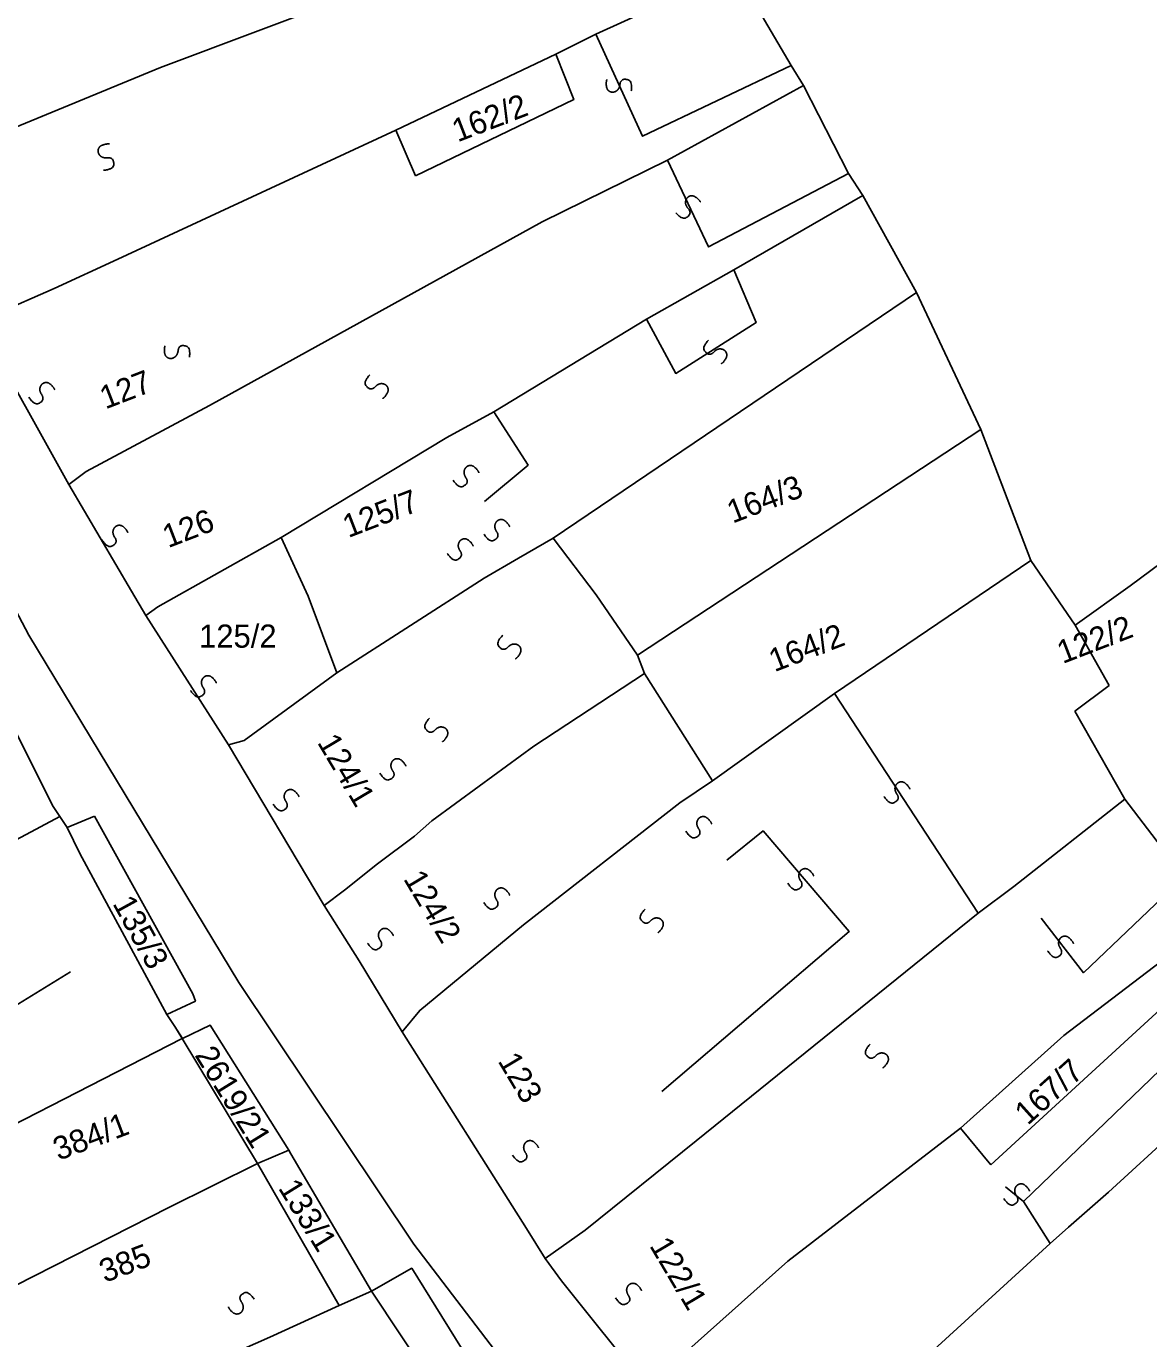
# Model space of a CAD drawing. Extents: x -581999 to -572728, y -1219553 to -1212032.
# Drawn here: x -577479.6 to -577382.6, y -1215803.1 to -1215689.6 of the extents above; entities that cross this region are included whole.
import ezdxf

# ---------------------------------------------------------------- set-up
doc = ezdxf.new("R2010")
doc.units = 0
for name, color, linetype in [('Vrstva 1', 7, 'Continuous'), ('Vrstva 2', 7, 'Continuous'), ('Vrstva 4', 7, 'Continuous'), ('Vrstva 6', 7, 'Continuous')]:
    doc.layers.add(name, color=color, linetype=linetype)

msp = doc.modelspace()

# ---------------------------------------------------------------- linework, layer by layer
at = {"layer": 'Vrstva 1'}
for p, q in [((-577474.479, -1215728.124), (-577475.958, -1215729.249)), ((-577468.275, -1215739.842), (-577469.308, -1215740.589)), ((-577481.907, -1215747.92), (-577477.385, -1215757.007)), ((-577460.819, -1215751.383), (-577462.159, -1215751.762)), ((-577477.385, -1215757.007), (-577476.755, -1215757.963)), ((-577507.598, -1215774.39), (-577476.755, -1215757.963)), ((-577476.123, -1215758.918), (-577476.755, -1215757.963)), ((-577476.123, -1215758.918), (-577473.744, -1215757.93)), ((-577473.744, -1215757.93), (-577465.258, -1215773.299)), ((-577475.024, -1215761.158), (-577476.123, -1215758.918)), ((-577452.134, -1215764.323), (-577453.896, -1215765.669)), ((-577421.749, -1215786.002), (-577397.389, -1215766.323)), ((-577431.335, -1215793.716), (-577421.749, -1215786.002)), ((-577431.335, -1215793.716), (-577434.793, -1215796.187))]:
    msp.add_line(p, q, dxfattribs=at)
for points in [[(-577468.038, -1215693.198), (-577433.831, -1215680.339), (-577425.062, -1215680.368), (-577420.535, -1215682.912), (-577418.354, -1215684.817)], [(-577418.354, -1215684.817), (-577430.438, -1215690.313)], [(-577418.354, -1215684.817), (-577413.545, -1215693.037)], [(-577430.438, -1215690.313), (-577433.893, -1215692.041)], [(-577433.893, -1215692.041), (-577447.706, -1215698.639)], [(-577445.994, -1215702.58), (-577432.338, -1215695.982), (-577433.893, -1215692.041)], [(-577415.225, -1215820.765), (-577417.003, -1215818.866), (-577424.293, -1215809.474), (-577425.981, -1215807.36), (-577433.385, -1215798.112), (-577434.793, -1215796.187), (-577436.416, -1215793.567), (-577447.16, -1215776.59), (-577450.88, -1215770.44), (-577453.896, -1215765.669), (-577462.159, -1215751.762), (-577469.308, -1215740.589), (-577470.545, -1215738.478), (-577475.958, -1215729.249), (-577483.606, -1215715.574), (-577485.422, -1215712.277), (-577489.417, -1215702.652), (-577494.758, -1215693.186)], [(-577488.601, -1215701.674), (-577468.038, -1215693.198)], [(-577413.545, -1215693.037), (-577412.464, -1215694.765)], [(-577424.24, -1215701.209), (-577412.464, -1215694.765)], [(-577412.464, -1215694.765), (-577408.591, -1215702.365)], [(-577447.706, -1215698.639), (-577471.725, -1215709.791), (-577477.219, -1215712.305)], [(-577445.994, -1215702.58), (-577447.706, -1215698.639)], [(-577435.07, -1215706.551), (-577424.24, -1215701.209)], [(-577408.591, -1215702.365), (-577407.35, -1215704.266)], [(-577407.35, -1215704.266), (-577418.498, -1215710.713)], [(-577402.699, -1215712.659), (-577407.35, -1215704.266)], [(-577463.808, -1215722.432), (-577435.07, -1215706.551)], [(-577496.282, -1215710.3), (-577479.426, -1215742.275), (-577461.278, -1215772.317), (-577446.155, -1215794.936), (-577420.966, -1215827.922), (-577400.326, -1215855.892), (-577397.913, -1215860.961)], [(-577418.498, -1215710.713), (-577426.034, -1215714.958)], [(-577477.219, -1215712.305), (-577482.242, -1215714.502)], [(-577434.118, -1215733.903), (-577402.699, -1215712.659)], [(-577397.141, -1215724.499), (-577402.699, -1215712.659)], [(-577426.034, -1215714.958), (-577439.227, -1215722.98)], [(-577474.479, -1215728.124), (-577463.808, -1215722.432)], [(-577439.227, -1215722.98), (-577443.31, -1215725.181)], [(-577426.826, -1215744.009), (-577397.141, -1215724.499)], [(-577392.841, -1215735.842), (-577397.141, -1215724.499)], [(-577443.31, -1215725.181), (-577457.602, -1215733.833)], [(-577457.602, -1215733.833), (-577468.275, -1215739.842)], [(-577457.602, -1215733.833), (-577455.28, -1215738.899)], [(-577437.102, -1215735.633), (-577434.118, -1215733.903)], [(-577430.398, -1215738.784), (-577434.118, -1215733.903)], [(-577440.085, -1215737.362), (-577437.102, -1215735.633)], [(-577409.804, -1215747.327), (-577392.841, -1215735.842)], [(-577392.841, -1215735.842), (-577389.002, -1215741.426)], [(-577384.258, -1215738.017), (-577380.685, -1215735.373)], [(-577452.809, -1215745.544), (-577440.085, -1215737.362)], [(-577389.002, -1215741.426), (-577384.258, -1215738.017)], [(-577455.28, -1215738.899), (-577452.809, -1215745.544)], [(-577426.826, -1215744.009), (-577430.398, -1215738.784)], [(-577389.002, -1215741.426), (-577386.058, -1215746.649)], [(-577426.208, -1215745.591), (-577426.826, -1215744.009)], [(-577460.819, -1215751.383), (-577452.809, -1215745.544)], [(-577435.789, -1215751.885), (-577426.208, -1215745.591)], [(-577420.331, -1215754.882), (-577426.208, -1215745.591)], [(-577386.058, -1215746.649), (-577389.043, -1215748.853)], [(-577409.804, -1215747.327), (-577420.331, -1215754.882)], [(-577389.043, -1215748.853), (-577384.704, -1215756.449)], [(-577440.499, -1215755.34), (-577435.789, -1215751.885)], [(-577423.157, -1215756.77), (-577420.331, -1215754.882)], [(-577444.59, -1215758.339), (-577440.499, -1215755.34)], [(-577360.719, -1215755.42), (-577396.277, -1215788.068)], [(-577436.674, -1215767.319), (-577423.157, -1215756.77)], [(-577384.704, -1215756.449), (-577394.29, -1215764.005)], [(-577384.704, -1215756.449), (-577379.584, -1215763.188)], [(-577446.104, -1215759.665), (-577444.59, -1215758.339)], [(-577358.87, -1215757.912), (-577393.478, -1215791.234)], [(-577449.285, -1215762.063), (-577446.104, -1215759.665)], [(-577467.49, -1215775.069), (-577475.024, -1215761.158)], [(-577452.134, -1215764.323), (-577449.285, -1215762.063)], [(-577394.29, -1215764.005), (-577397.389, -1215766.323)], [(-577447.16, -1215776.59), (-577445.634, -1215774.72), (-577436.674, -1215767.319)], [(-577376.787, -1215766.829), (-577389.984, -1215776.902), (-577398.919, -1215784.902)], [(-577465.258, -1215773.299), (-577465.025, -1215773.915), (-577467.49, -1215775.069)], [(-577467.49, -1215775.069), (-577466.813, -1215776.114)], [(-577466.813, -1215776.114), (-577466.144, -1215777.146)], [(-577466.18, -1215777.164), (-577466.813, -1215776.114)], [(-577466.144, -1215777.146), (-577463.764, -1215775.991), (-577456.952, -1215786.805)], [(-577490.032, -1215789.369), (-577466.18, -1215777.164)], [(-577466.18, -1215777.164), (-577466.144, -1215777.146)], [(-577459.671, -1215787.958), (-577466.18, -1215777.164)], [(-577398.919, -1215784.902), (-577413.845, -1215796.392)], [(-577396.277, -1215788.068), (-577398.919, -1215784.902)], [(-577386.114, -1215790.453), (-577380.336, -1215785.123)], [(-577459.671, -1215787.958), (-577456.952, -1215786.805)], [(-577456.952, -1215786.805), (-577456.785, -1215787.123), (-577449.81, -1215798.999)], [(-577467.321, -1215791.752), (-577459.671, -1215787.958)], [(-577452.614, -1215800.25), (-577459.671, -1215787.958)], [(-577391.151, -1215794.873), (-577393.478, -1215791.234)], [(-577389.591, -1215793.467), (-577386.114, -1215790.453)], [(-577480.581, -1215798.517), (-577467.321, -1215791.752)], [(-577391.151, -1215794.873), (-577389.591, -1215793.467)], [(-577408.917, -1215811.092), (-577391.151, -1215794.873)], [(-577449.81, -1215798.999), (-577446.325, -1215797.019), (-577434.643, -1215815.868), (-577437.449, -1215817.602)], [(-577413.845, -1215796.392), (-577422.648, -1215804.265)], [(-577452.614, -1215800.25), (-577449.81, -1215798.999)], [(-577437.449, -1215817.602), (-577449.81, -1215798.999)], [(-577458.586, -1215802.977), (-577452.614, -1215800.25)], [(-577472.01, -1215808.911), (-577458.586, -1215802.977)]]:
    msp.add_lwpolyline(points, dxfattribs=at)
at = {"layer": 'Vrstva 4'}
for points in [[(-577430.438, -1215690.313), (-577426.404, -1215699.147), (-577413.545, -1215693.037)], [(-577424.24, -1215701.209), (-577420.687, -1215708.719), (-577408.591, -1215702.365)], [(-577426.034, -1215714.958), (-577423.514, -1215719.662), (-577416.569, -1215715.256), (-577418.498, -1215710.713)], [(-577439.227, -1215722.98), (-577436.277, -1215727.575), (-577440.05, -1215730.724)], [(-577397.389, -1215766.323), (-577409.804, -1215747.327)], [(-577419.112, -1215761.723), (-577415.968, -1215759.204), (-577408.526, -1215767.893), (-577424.719, -1215781.751)], [(-577391.935, -1215766.756), (-577388.277, -1215771.472), (-577379.584, -1215763.188)], [(-577475.827, -1215771.391), (-577481.441, -1215774.858)], [(-577393.478, -1215791.234), (-577395.035, -1215789.966)]]:
    msp.add_lwpolyline(points, dxfattribs=at)
at = {"layer": 'Vrstva 6'}
for points in [[(-577427.357, -1215695.227), (-577427.262, -1215694.376), (-577427.992, -1215694.164), (-577428.309, -1215694.418), (-577428.354, -1215694.834), (-577428.505, -1215695.141), (-577428.754, -1215695.308), (-577428.981, -1215695.352), (-577429.244, -1215695.296), (-577429.499, -1215695.032), (-577429.539, -1215694.422), (-577429.469, -1215694.253)], [(-577472.967, -1215702.095), (-577472.116, -1215702.006), (-577472.064, -1215701.248), (-577472.38, -1215700.992), (-577472.796, -1215701.037), (-577473.128, -1215700.955), (-577473.345, -1215700.747), (-577473.436, -1215700.535), (-577473.437, -1215700.266), (-577473.234, -1215699.961), (-577472.646, -1215699.791), (-577472.466, -1215699.824)], [(-577423.513, -1215705.765), (-577422.937, -1215706.397), (-577422.295, -1215705.99), (-577422.276, -1215705.584), (-577422.559, -1215705.276), (-577422.689, -1215704.959), (-577422.65, -1215704.661), (-577422.533, -1215704.462), (-577422.317, -1215704.302), (-577421.951, -1215704.285), (-577421.466, -1215704.658), (-577421.386, -1215704.823)], [(-577465.54, -1215718.251), (-577465.445, -1215717.4), (-577466.175, -1215717.188), (-577466.492, -1215717.442), (-577466.537, -1215717.858), (-577466.688, -1215718.165), (-577466.937, -1215718.332), (-577467.164, -1215718.376), (-577467.427, -1215718.32), (-577467.682, -1215718.056), (-577467.722, -1215717.446), (-577467.652, -1215717.277)], [(-577420.679, -1215716.769), (-577421.266, -1215717.391), (-577420.811, -1215718), (-577420.405, -1215717.988), (-577420.119, -1215717.683), (-577419.813, -1215717.529), (-577419.513, -1215717.545), (-577419.306, -1215717.647), (-577419.13, -1215717.85), (-577419.085, -1215718.214), (-577419.42, -1215718.726), (-577419.578, -1215718.818)], [(-577449.941, -1215719.77), (-577450.528, -1215720.392), (-577450.073, -1215721.001), (-577449.667, -1215720.989), (-577449.381, -1215720.684), (-577449.075, -1215720.53), (-577448.775, -1215720.546), (-577448.568, -1215720.648), (-577448.392, -1215720.851), (-577448.347, -1215721.215), (-577448.682, -1215721.727), (-577448.84, -1215721.819)], [(-577479.422, -1215721.708), (-577478.942, -1215722.415), (-577478.248, -1215722.104), (-577478.171, -1215721.704), (-577478.407, -1215721.359), (-577478.492, -1215721.027), (-577478.41, -1215720.737), (-577478.266, -1215720.557), (-577478.03, -1215720.429), (-577477.665, -1215720.465), (-577477.238, -1215720.904), (-577477.183, -1215721.077)], [(-577442.765, -1215728.881), (-577442.285, -1215729.588), (-577441.591, -1215729.277), (-577441.514, -1215728.877), (-577441.75, -1215728.532), (-577441.835, -1215728.2), (-577441.753, -1215727.91), (-577441.609, -1215727.73), (-577441.373, -1215727.602), (-577441.008, -1215727.638), (-577440.581, -1215728.077), (-577440.526, -1215728.25)], [(-577440.105, -1215733.55), (-577439.625, -1215734.257), (-577438.931, -1215733.946), (-577438.854, -1215733.546), (-577439.09, -1215733.201), (-577439.175, -1215732.869), (-577439.093, -1215732.579), (-577438.949, -1215732.399), (-577438.713, -1215732.271), (-577438.348, -1215732.307), (-577437.921, -1215732.746), (-577437.866, -1215732.919)], [(-577473.104, -1215734.049), (-577472.624, -1215734.756), (-577471.93, -1215734.445), (-577471.853, -1215734.045), (-577472.089, -1215733.7), (-577472.174, -1215733.368), (-577472.092, -1215733.078), (-577471.948, -1215732.898), (-577471.712, -1215732.77), (-577471.347, -1215732.806), (-577470.92, -1215733.245), (-577470.865, -1215733.418)], [(-577443.264, -1215735.218), (-577442.784, -1215735.925), (-577442.09, -1215735.614), (-577442.013, -1215735.214), (-577442.249, -1215734.869), (-577442.334, -1215734.537), (-577442.252, -1215734.247), (-577442.108, -1215734.067), (-577441.872, -1215733.939), (-577441.507, -1215733.975), (-577441.08, -1215734.414), (-577441.025, -1215734.587)], [(-577438.469, -1215742.283), (-577439.056, -1215742.905), (-577438.601, -1215743.514), (-577438.195, -1215743.502), (-577437.909, -1215743.197), (-577437.603, -1215743.043), (-577437.303, -1215743.059), (-577437.096, -1215743.161), (-577436.92, -1215743.364), (-577436.875, -1215743.728), (-577437.21, -1215744.24), (-577437.368, -1215744.332)], [(-577465.457, -1215747.056), (-577464.977, -1215747.763), (-577464.283, -1215747.452), (-577464.206, -1215747.052), (-577464.442, -1215746.707), (-577464.527, -1215746.375), (-577464.445, -1215746.085), (-577464.301, -1215745.905), (-577464.065, -1215745.777), (-577463.7, -1215745.813), (-577463.273, -1215746.252), (-577463.218, -1215746.425)], [(-577444.788, -1215749.453), (-577445.375, -1215750.075), (-577444.92, -1215750.684), (-577444.514, -1215750.672), (-577444.228, -1215750.367), (-577443.922, -1215750.213), (-577443.622, -1215750.229), (-577443.415, -1215750.331), (-577443.239, -1215750.534), (-577443.194, -1215750.898), (-577443.529, -1215751.41), (-577443.687, -1215751.502)], [(-577449.083, -1215754.229), (-577448.603, -1215754.936), (-577447.909, -1215754.625), (-577447.832, -1215754.225), (-577448.068, -1215753.88), (-577448.153, -1215753.548), (-577448.071, -1215753.258), (-577447.927, -1215753.078), (-577447.691, -1215752.95), (-577447.326, -1215752.986), (-577446.899, -1215753.425), (-577446.844, -1215753.598)], [(-577405.523, -1215756.23), (-577405.043, -1215756.937), (-577404.349, -1215756.626), (-577404.272, -1215756.226), (-577404.508, -1215755.881), (-577404.593, -1215755.549), (-577404.511, -1215755.259), (-577404.367, -1215755.079), (-577404.131, -1215754.951), (-577403.766, -1215754.987), (-577403.339, -1215755.426), (-577403.284, -1215755.599)], [(-577458.307, -1215756.895), (-577457.827, -1215757.602), (-577457.133, -1215757.291), (-577457.056, -1215756.891), (-577457.292, -1215756.546), (-577457.377, -1215756.214), (-577457.295, -1215755.924), (-577457.151, -1215755.744), (-577456.915, -1215755.616), (-577456.55, -1215755.652), (-577456.123, -1215756.091), (-577456.068, -1215756.264)], [(-577422.648, -1215759.232), (-577422.168, -1215759.939), (-577421.474, -1215759.628), (-577421.397, -1215759.228), (-577421.633, -1215758.883), (-577421.718, -1215758.551), (-577421.636, -1215758.261), (-577421.492, -1215758.081), (-577421.256, -1215757.953), (-577420.891, -1215757.989), (-577420.464, -1215758.428), (-577420.409, -1215758.601)], [(-577413.836, -1215763.735), (-577413.356, -1215764.442), (-577412.662, -1215764.131), (-577412.585, -1215763.731), (-577412.821, -1215763.386), (-577412.906, -1215763.054), (-577412.824, -1215762.764), (-577412.68, -1215762.584), (-577412.444, -1215762.456), (-577412.079, -1215762.492), (-577411.652, -1215762.931), (-577411.597, -1215763.104)], [(-577440.105, -1215765.402), (-577439.625, -1215766.109), (-577438.931, -1215765.798), (-577438.854, -1215765.398), (-577439.09, -1215765.053), (-577439.175, -1215764.721), (-577439.093, -1215764.431), (-577438.949, -1215764.251), (-577438.713, -1215764.123), (-577438.348, -1215764.159), (-577437.921, -1215764.598), (-577437.866, -1215764.771)], [(-577426.166, -1215765.963), (-577426.753, -1215766.585), (-577426.298, -1215767.194), (-577425.892, -1215767.182), (-577425.606, -1215766.877), (-577425.3, -1215766.723), (-577425, -1215766.739), (-577424.793, -1215766.841), (-577424.617, -1215767.044), (-577424.572, -1215767.408), (-577424.907, -1215767.92), (-577425.065, -1215768.012)], [(-577450.16, -1215768.901), (-577449.68, -1215769.608), (-577448.986, -1215769.297), (-577448.909, -1215768.897), (-577449.145, -1215768.552), (-577449.23, -1215768.22), (-577449.148, -1215767.93), (-577449.004, -1215767.75), (-577448.768, -1215767.622), (-577448.403, -1215767.658), (-577447.976, -1215768.097), (-577447.921, -1215768.27)], [(-577391.39, -1215769.571), (-577390.91, -1215770.278), (-577390.216, -1215769.967), (-577390.139, -1215769.567), (-577390.375, -1215769.222), (-577390.46, -1215768.89), (-577390.378, -1215768.6), (-577390.234, -1215768.42), (-577389.998, -1215768.292), (-577389.633, -1215768.328), (-577389.206, -1215768.767), (-577389.151, -1215768.94)], [(-577406.713, -1215777.636), (-577407.3, -1215778.258), (-577406.845, -1215778.867), (-577406.439, -1215778.855), (-577406.153, -1215778.55), (-577405.847, -1215778.396), (-577405.547, -1215778.412), (-577405.34, -1215778.514), (-577405.164, -1215778.717), (-577405.119, -1215779.081), (-577405.454, -1215779.593), (-577405.612, -1215779.685)], [(-577437.611, -1215787.248), (-577437.131, -1215787.955), (-577436.437, -1215787.644), (-577436.36, -1215787.244), (-577436.596, -1215786.899), (-577436.681, -1215786.567), (-577436.599, -1215786.277), (-577436.455, -1215786.097), (-577436.219, -1215785.969), (-577435.854, -1215786.005), (-577435.427, -1215786.444), (-577435.372, -1215786.617)], [(-577395.178, -1215790.986), (-577394.698, -1215791.693), (-577394.004, -1215791.382), (-577393.927, -1215790.982), (-577394.163, -1215790.637), (-577394.248, -1215790.305), (-577394.166, -1215790.015), (-577394.022, -1215789.835), (-577393.786, -1215789.707), (-577393.421, -1215789.743), (-577392.994, -1215790.182), (-577392.939, -1215790.355)], [(-577428.712, -1215799.586), (-577428.232, -1215800.293), (-577427.538, -1215799.982), (-577427.461, -1215799.582), (-577427.697, -1215799.237), (-577427.782, -1215798.905), (-577427.7, -1215798.615), (-577427.556, -1215798.435), (-577427.32, -1215798.307), (-577426.955, -1215798.343), (-577426.528, -1215798.782), (-577426.473, -1215798.955)], [(-577459.956, -1215799.678), (-577460.452, -1215798.98), (-577461.138, -1215799.307), (-577461.205, -1215799.708), (-577460.962, -1215800.048), (-577460.871, -1215800.378), (-577460.945, -1215800.668), (-577461.085, -1215800.852), (-577461.319, -1215800.985), (-577461.685, -1215800.958), (-577462.121, -1215800.529), (-577462.181, -1215800.357)]]:
    msp.add_open_spline(points, degree=2, dxfattribs=at)

# ---------------------------------------------------------------- texts
at = {"layer": 'Vrstva 2'}
for s, rotation, p in [('162/2', 21.05858, (-577442.366, -1215699.687)), ('127', 21.05858, (-577472.802, -1215722.775)), ('164/3', 21.05858, (-577418.603, -1215732.648)), ('125/7', 21.05858, (-577451.816, -1215733.895)), ('126', 21.05858, (-577467.383, -1215734.771)), ('164/2', 21.05858, (-577414.989, -1215745.496)), ('122/2', 21.05858, (-577390.081, -1215744.784)), ('124/1', 300.74266, (-577454.543, -1215751.555)), ('124/2', 300.74266, (-577447.097, -1215763.351)), ('135/3', 298.80407, (-577472.226, -1215765.483)), ('2619/21', 301.73512, (-577465.137, -1215778.592)), ('123', 300.74266, (-577438.937, -1215779.098)), ('167/7', 41.95669, (-577393.104, -1215784.719)), ('384/1', 20.76362, (-577476.855, -1215787.737)), ('133/1', 301.73512, (-577457.919, -1215790.08)), ('385', 20.76362, (-577472.856, -1215798.292)), ('122/1', 300.74266, (-577425.837, -1215795.065))]:
    msp.add_text(s, height=2, rotation=rotation, dxfattribs=at).set_placement(p)
msp.add_text('125/2', height=2, dxfattribs=at).set_placement((-577464.708, -1215743.366))

doc.saveas('drawing.dxf')
